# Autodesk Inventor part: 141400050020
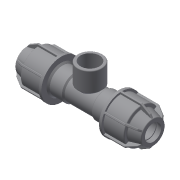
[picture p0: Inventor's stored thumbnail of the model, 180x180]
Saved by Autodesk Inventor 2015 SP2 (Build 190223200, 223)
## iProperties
Created: 2017-08
Part Number: 141400050020
Material: Generic
Description: PLASSON L.14 TEE FEMALE ADAPTOR (SILVER) 50 x 2" x 50
Document SubType Name: Modeling
Designer: KIM
Density: 1 g/cm^3
Appearance: Default
Author: KIM
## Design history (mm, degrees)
derived "141400.ipt"
feature "Solid1::141400.ipt"
feature "Solid2::141400.ipt"
tag "TaggingFeature1"
body "Solid1"
other parameters: "d2" = 72, "d4" = 15 deg, "d5" = 47.52, "d6" = 15.6816, "d10" = 92, "d16" = 51, "d17" = 3.6, "d24" = 3.6, "d25" = 82.8, "d26" = 69, "d27" = 3.6, "d28" = 135 deg, "d29" = 2.16, "d31" = 2.5, "d46" = 150 deg, "d49" = 4.6, "d50" = 0, "d58" = 1.5, "d61" = 360 deg, "d63" = 45, "d80" = 72, "d81" = 4, "d84" = 3.6, "d94" = 79, "d95" = 56.656, "d96" = 73.6528, "d98" = 45, "d99" = 51.55696, "d100" = 135 deg, "d108" = 2.5, "d111" = 0, "G_" = 56.656, "E_" = 92, "l_" = 72, "A_" = 79
